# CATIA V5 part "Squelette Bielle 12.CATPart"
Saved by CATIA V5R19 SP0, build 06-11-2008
Part number: Squelette bielle 12
Publications: "Droite D (bielle 12)", "Droite C (bielle 12)", "Droite E (bielle 12)", "Droite CD (bielle 12)", "Droite CE (bielle 12)", "Plan.3", "Plan.4", "Point.4", "Plan.6", "Plan.7"
Bounding box of the stored display mesh (mm): x -2 to 32, y 35 to 89, z -50 to 50
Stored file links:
  G:\EU_thinkMotion\CFAO_2010\MMS_groupe3\MMS_groupe3\A reprendre\lpastor\lpastor\Squelette Bielle 12.CATPart
  C:\Users\Loïc\Documents\IFMA\Cours 2A\CFAO\Thinkmotion\Fourche avant.CATProduct
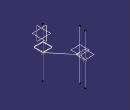
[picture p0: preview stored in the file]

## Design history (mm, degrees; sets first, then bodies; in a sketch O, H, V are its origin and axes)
Set1
  Point1 "D": linked copy from another document
  Point2 "C": linked copy from another document
  Point3 "E": linked copy from another document
Set2 "Set géométrique bielle 12"
  Line1 "Droite D (bielle 12)": type PtDir, RefPoint Point1, Direction xy-plane, Start -50, End 50
  Line2 "Droite C (bielle 12)": type PtDir, RefPoint Point2, Direction xy-plane, Start -50, End 50
  Line3 "Droite E (bielle 12)": type PtDir, RefPoint Point3, Direction xy-plane, Start -50, End 50
  Line4 "Droite CD (bielle 12)": type PtPt, FirstPoint Point1, SecondPoint Point2
  Line5 "Droite CE (bielle 12)": type PtPt, FirstPoint Point2, SecondPoint Point3
  Plane1: type Normal, Curve Line1, RefPoint Point1
  Plane2: type Normal, Curve Line2, RefPoint Point2
  Plane3: type Offset, RefPlane Plane1, Offset 8
  Plane4: type Offset, RefPlane Plane2, Offset 8
  Plane5: type Normal, Curve Line3, RefPoint Point3
  Plane6: type Offset, RefPlane Plane5, Offset 10
  Plane7: type Offset, RefPlane Plane5, Offset 9
Body1 (main body)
